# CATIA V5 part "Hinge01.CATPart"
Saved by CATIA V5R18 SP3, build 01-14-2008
Part number: Hinge 03
Bounding box of the stored display mesh (mm): x -40 to 40, y -15 to 15, z -14 to 14
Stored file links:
  E:\#00 CATIA V5 Movie\#03 CATIA V5 Data\#07 KIN\Balance Unit (1)\Hinge01.CATPart
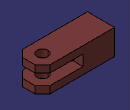
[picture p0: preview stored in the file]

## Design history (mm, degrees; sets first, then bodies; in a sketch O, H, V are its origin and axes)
Body1 (main body)
  Sketch1 on xy-plane, origin (0, 0, 0), H (1, 0, 0), V (0, 1, 0)
    line L1 (40, 7) -> (40, -7)
    line L2 (32, -15) -> (-40, -15)
    line L3 (-40, -15) -> (-40, 15)
    line L4 (-40, 15) -> (32, 15)
    point P1 (40, 15)
    point P2 (40, -15)
    point P4 (-40, 15)
    line L5 (40, 7) -> (32, 15)
    point P5 (40, 7)
    point P6 (32, 15)
    line L6 (40, -7) -> (32, -15)
    point P7 (40, -7)
    point P8 (32, -15)
    circle A1 centre (25, 0) radius 6
    point P9 (25, 0)
    distance P1 P2 = 30
    distance P4 P1 = 80
    distance P5 P1 = 8
    distance P6 P1 = 8
    distance P7 P2 = 8 {= Sketch1.distance(P5 P1)}
    distance P8 P2 = 8 {= Sketch1.distance(P6 P1)}
    distance P9 L3 = 65
    radius A1 = 6
    vertical: L1 V, L3 V
    horizontal: L2 H, L4 H
    equidistance: L1 L3 O, L2 L4 O
    coincidence: L1 P1, L4 P1, L1 P2, L2 P2, P9 H
  Pad1: profile Sketch1, direction (0, 0, 1), length 14, mirrored extent
  Sketch2 on face of Pad1 from Sketch1.L4, origin (0, 15, 0), H (-1, 0, 0), V (0, 0, 1)
    line L1 (-40, 6) -> (5, 6)
    line L2 (5, 6) -> (5, -6)
    line L3 (5, -6) -> (-40, -6)
    line L4 (-40, -6) -> (-40, 6)
    reference intersected line E1 through (-40, 0) direction (0, 1) from face of Pad1 from Sketch1.L1
    distance L2 L4 = 45
    length L4 = 12
    horizontal: L1 H, L3 H
    vertical: L2 V, L4 V
    coincidence: L4 E1
    symmetry: L1 L3 H
  Pocket1: profile Sketch2, direction (0, -1, 0), through (limit type 6)
  Sketch3 on face of Pad1 from Sketch1.L3, origin (-40, 0, 0), H (0, 1, 0), V (0, 0, -1)
    point P1 (0, 0)
    reference projected point E1 (0, 0) from Sketch4.P1
    coincidence: E1 P1
  Hole1: placed by Sketch3, at (-40, 0, 0) direction (1, 0, 0), diameter 13.835, depth 37, V-bottom angle 120, threaded "M16", thread diameter 16, thread depth 35, pitch 2
  Sketch4 on face of Pad1 from Sketch1.L3, origin (-40, 0, 0), H (0, -1, 0), V (0, 0, 1)
    point P1 (0, 0)
    coincidence: P1 O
